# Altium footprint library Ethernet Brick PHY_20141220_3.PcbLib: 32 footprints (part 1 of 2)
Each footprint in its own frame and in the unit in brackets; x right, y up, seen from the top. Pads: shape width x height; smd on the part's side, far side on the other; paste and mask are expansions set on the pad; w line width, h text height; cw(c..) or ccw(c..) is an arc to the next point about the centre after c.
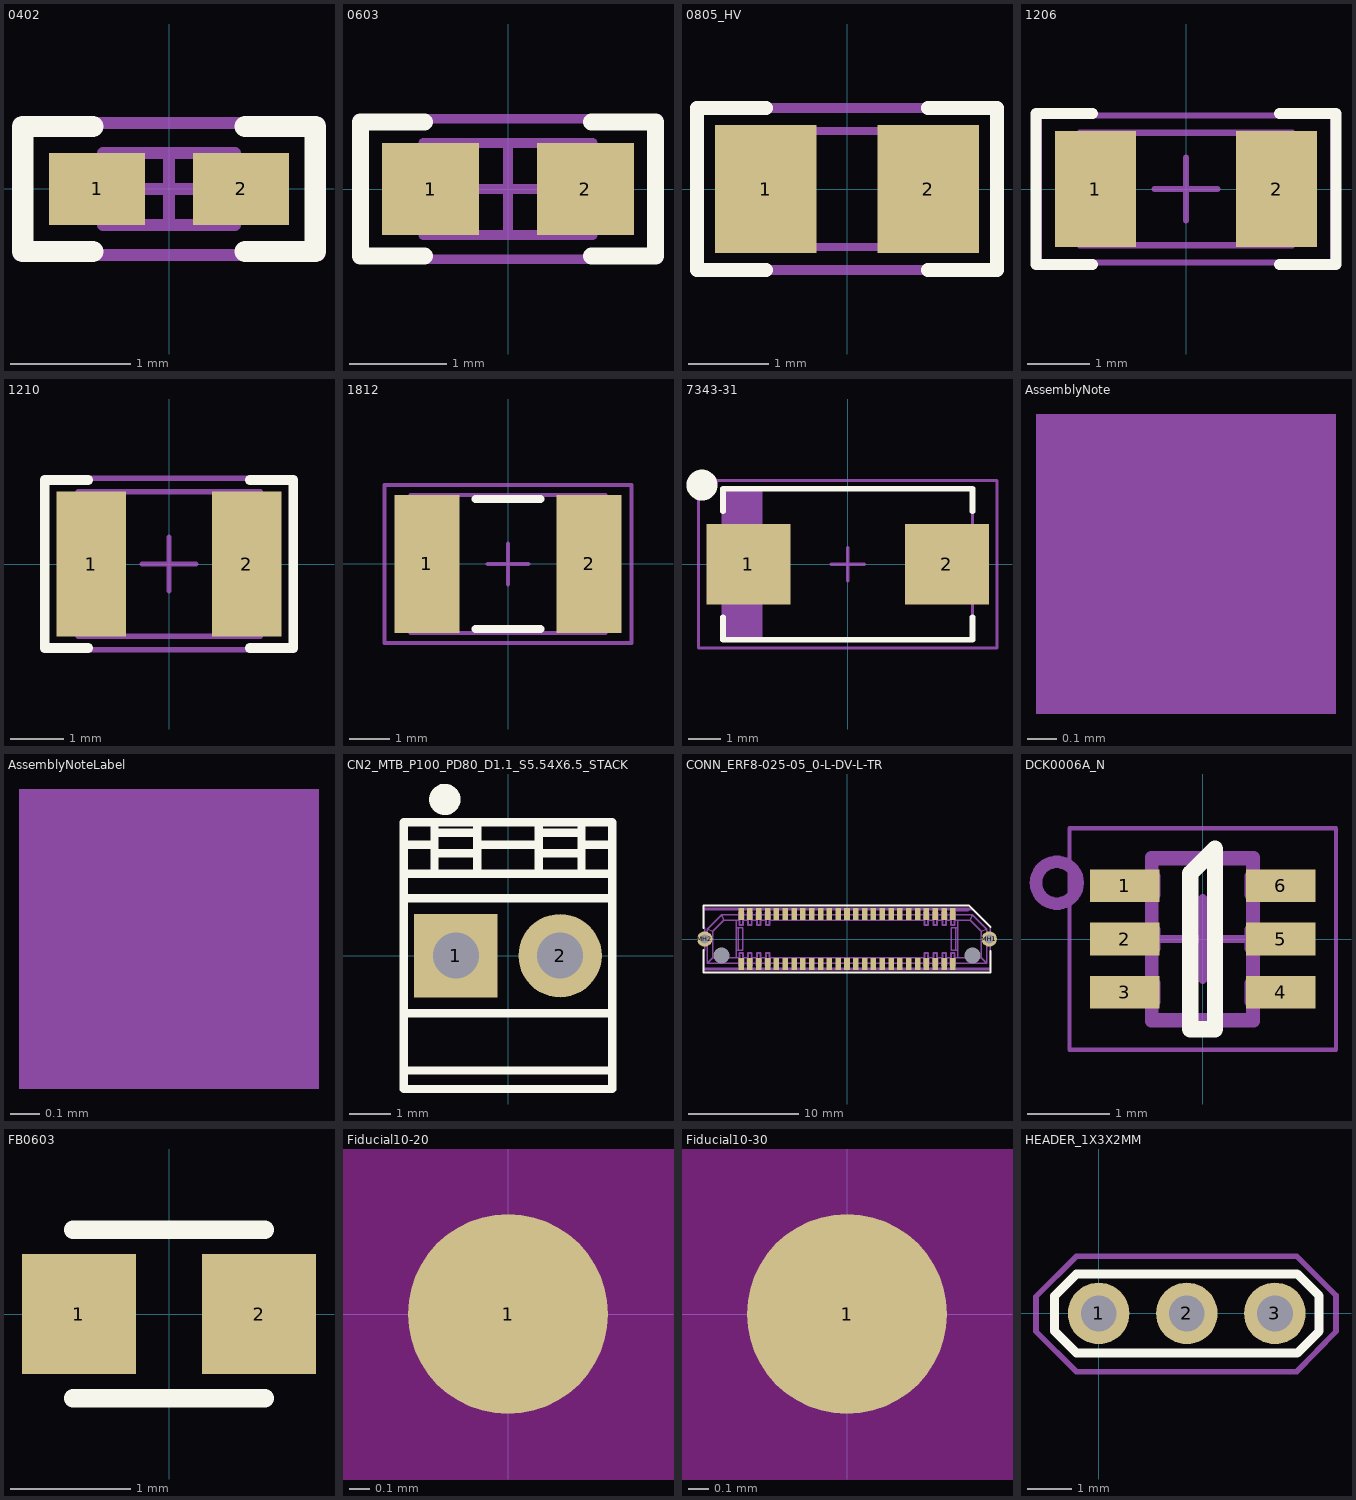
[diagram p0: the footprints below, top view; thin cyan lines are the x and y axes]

## 0402 [mm] "0402 from SM-752 data"
height 0.6
pads (2):
  rect 0.8x0.6 smd: 1(-0.6,0) 2(0.6,0)
Top Overlay:
  lines w0.178: -0.635,-0.521 -1.219,-0.521 -1.219,0.521 -0.635,0.521 ; 0.635,-0.521 1.219,-0.521 1.219,0.521 0.635,0.521
Mechanical 5:
  lines w0.1: -1.25,-0.55 1.25,-0.55 1.25,0.55 -1.25,0.55 -1.25,-0.55
  text ".Designator" at 2.502,-2.032 h0.91
Mechanical 13:
  lines w0.1: -0.35,-0.3 -0.35,0.3 ; 0.35,-0.3 0.35,0.3 ; -0.55,-0.3 -0.55,0.3 0.55,0.3 0.55,-0.3 -0.55,-0.3
Mechanical 15:
  lines w0.1: -0.3,0 0.3,0 ; 0,-0.3 0,0.3 ; -1.25,-0.55 -1.25,0.55 1.25,0.55 1.25,-0.55 -1.25,-0.55
3D body: height 0.6, standoff 0, extent -0.549,-0.299 -0.351,0.299
3D body: height 0.6, standoff 0, extent -0.349,-0.299 0.349,0.299
3D body: height 0.6, standoff 0, extent 0.351,-0.299 0.549,0.299

## 0603 [mm] "0603 from SM-752 data"
height 0.85
pads (2):
  rect 1x0.95 smd: 1(-0.8,0) 2(0.8,0)
Top Overlay:
  lines w0.178: -0.864,-0.691 -1.524,-0.691 -1.524,0.693 -0.864,0.693 ; 0.864,-0.691 1.524,-0.691 1.524,0.693 0.864,0.693
Mechanical 5:
  lines w0.1: -1.55,-0.725 -1.55,0.725 1.55,0.725 1.55,-0.725 -1.55,-0.725
  text ".Designator" at -0.813,-0.432 h0.91
Mechanical 13:
  lines w0.1: -0.55,-0.475 -0.55,0.475 ; 0.55,-0.475 0.55,0.475 ; -0.875,-0.475 0.875,-0.475 0.875,0.475 -0.875,0.475 -0.875,-0.475
Mechanical 15:
  lines w0.1: -0.475,0 0.475,0 ; 0,-0.475 0,0.475 ; -1.55,-0.725 1.55,-0.725 1.55,0.725 -1.55,0.725 -1.55,-0.725
3D body: height 0.85, standoff 0, extent -0.874,-0.474 -0.551,0.474
3D body: height 0.85, standoff 0, extent -0.549,-0.474 0.549,0.474
3D body: height 0.85, standoff 0, extent 0.551,-0.474 0.874,0.474

## 0805_HV [mil] "0805 with 30mil clearance between pads"
height 43.31
pads (2):
  rect 50x63 smd: 1(-40,0) 2(40,0)
Top Overlay:
  lines w7: -40,-40 -74,-40 -74,0 -74,40 -40,40 ; 40,-40 74,-40 74,0 74,40 40,40
Mechanical 5:
  lines w5: -74,-40 -74,40 74,40 74,-40 -74,-40
  text ".Designator" at 44,17.85 h36
Mechanical 13:
  lines w3.94: -25.59,-28.54 -25.59,28.54 ; 25.59,-28.54 25.59,28.54 ; -43.31,-28.54 43.31,-28.54 43.31,28.54 -43.31,28.54 -43.31,-28.54
3D body: height 43.31, standoff 0, extent -43.29,-28.52 -25.61,28.52
3D body: height 43.31, standoff 0, extent -25.57,-28.52 25.57,28.52
3D body: height 43.31, standoff 0, extent 25.61,-28.52 43.29,28.52

## 1206 [mm] "1206 from SM-752 data"
height 1.35
pads (2):
  rect 1.3x1.85 smd: 1(-1.45,0) 2(1.45,0)
Top Overlay:
  lines w0.178: -1.5,-1.21 -2.4,-1.21 -2.4,1.21 -1.5,1.21 ; 1.5,-1.21 2.4,-1.21 2.4,1.21 1.5,1.21
Mechanical 5:
  lines w0.1: -1.7,-0.9 1.7,-0.9 1.7,0.9 -1.7,0.9 -1.7,-0.9
  text ".Designator" at 0.711,0.457 h0.91
Mechanical 13:
  lines w0.1: -1.2,-0.9 -1.2,0.9 ; 1.2,-0.9 1.2,0.9 ; -1.7,-0.9 1.7,-0.9 1.7,0.9 -1.7,0.9 -1.7,-0.9
Mechanical 15:
  lines w0.1: -0.5,0 0.5,0 ; 0,-0.5 0,0.5 ; -2.35,-1.175 2.35,-1.175 2.35,1.175 -2.35,1.175 -2.35,-1.175
3D body: height 1.35, standoff 0, extent -1.699,-0.899 -1.201,0.899
3D body: height 1.35, standoff 0, extent -1.199,-0.899 1.199,0.899
3D body: height 1.35, standoff 0, extent 1.201,-0.899 1.699,0.899

## 1210 [mm] "1210 from SM-752 data"
height 1.35
pads (2):
  rect 1.3x2.7 smd: 1(-1.45,0) 2(1.45,0)
Top Overlay:
  lines w0.178: -1.511,-1.568 -2.316,-1.568 -2.316,1.568 -1.511,1.568 ; 1.511,-1.568 2.316,-1.568 2.316,1.568 1.511,1.568
Mechanical 5:
  lines w0.1: -1.7,-1.35 1.7,-1.35 1.7,1.35 -1.7,1.35 -1.7,-1.35
  text ".Designator" at 1.292,0.432 h0.91
Mechanical 13:
  lines w0.1: -1.2,-1.35 -1.2,1.35 ; 1.2,-1.35 1.2,1.35 ; -1.7,-1.35 -1.7,1.35 1.7,1.35 1.7,-1.35 -1.7,-1.35
Mechanical 15:
  lines w0.1: -0.5,0 0.5,0 ; 0,-0.5 0,0.5 ; -2.35,-1.6 -2.35,1.6 2.35,1.6 2.35,-1.6 -2.35,-1.6
3D body: height 1.35, standoff 0, extent -1.699,-1.349 -1.201,1.349
3D body: height 1.35, standoff 0, extent -1.199,-1.349 1.199,1.349
3D body: height 1.35, standoff 0, extent 1.201,-1.349 1.699,1.349

## 1812 [mm]
height 1.35
pads (2):
  rect 1.6x3.4 smd: 1(-2,0) 2(2,0)
Top Overlay:
  lines w0.2: -0.8,-1.6 0.8,-1.6 ; -0.8,1.6 0.8,1.6
Mechanical 5:
  lines w0.1: -2.4,-1.7 2.4,-1.7 2.4,1.7 -2.4,1.7 -2.4,-1.7
  text ".Designator" at -1.245,-0.406 h0.91
Mechanical 13:
  lines w0.1: -1.9,-1.7 -1.9,1.7 ; 1.9,-1.7 1.9,1.7 ; -2.4,-1.7 -2.4,1.7 2.4,1.7 2.4,-1.7 -2.4,-1.7
Mechanical 15:
  lines w0.1: -0.5,0 0.5,0 ; 0,-0.5 0,0.5 ; -3.05,-1.95 -3.05,1.95 3.05,1.95 3.05,-1.95 -3.05,-1.95
3D body: height 1.35, standoff 0, extent -2.399,-1.699 -1.901,1.699
3D body: height 1.35, standoff 0, extent -1.899,-1.699 1.899,1.699
3D body: height 1.35, standoff 0, extent 1.901,-1.699 2.399,1.699

## 7343-31 [mm] "Medium Density based on Kemet T495 dimensions"
height 3.1
pads (2):
  rect 2.55x2.45 smd: 1(-3.025,0) 2(3.025,0)
Top Overlay:
  circle w0.635: c-4.441,2.413 r0.152
  lines w0.178: -3.8,-1.614 -3.8,-2.3 3.8,-2.3 3.8,-1.614 ; -3.8,1.614 -3.8,2.3 3.8,2.3 3.8,1.614
Mechanical 5:
  rectangle: -3.8,-2.3 -2.65,2.3
  lines w0.1: -2.65,-2.3 -2.65,2.3 ; -3.8,-2.3 -3.8,2.3 3.8,2.3 3.8,-2.3 -3.8,-2.3
  text ".Designator" at -1.19,-0.457 h0.91
Mechanical 15:
  lines w0.1: -0.5,0 0.5,0 ; 0,-0.5 0,0.5 ; -4.55,-2.55 4.55,-2.55 4.55,2.55 -4.55,2.55 -4.55,-2.55
3D body: height 3.1, standoff 3.1, extent -3.799,-2.299 -2.651,2.299
3D body: height 3.1, standoff 0, extent -3.8,-2.3 3.8,2.3

## AssemblyNote [mm] "Assembly Note"
Mechanical 5:
  rectangle: -17.907,-39.319 -16.891,-38.303
  text ".Comment" at -16.256,-39.319 h0.91
  text ".Designator" at -21.59,-39.319 h0.91

## AssemblyNoteLabel [mm] "Assembly Note for PCB Labels"
Mechanical 5:
  rectangle: -17.907,-39.421 -16.891,-38.405
  text "Install label in silkscreened box after final wash.  Text shall be 8 pt font.  Text shall be per the Label Table in the PDF schematic." at -16.256,-39.421 h0.91
  text ".Designator" at -21.59,-39.421 h0.91

## CN2_MTB_P100_PD80_D1.1_S5.54X6.5_STACK [mil]
height 400
pads (2):
  rect 80x80 / inner round 80 / far side rect 80x80 hole 44: 1(-50,0)
  round 80 hole 44: 2(50,0)
Top Overlay:
  circle w10: c-60.63,149.95 r5
  circle w10: c-60.63,149.95 r10
  lines w8: -100,-110.24 100,-110.24 ; -100,-55.12 100,-55.12 ; -100,55.12 100,55.12 ; -100,78.74 100,78.74 ; -100,106.3 -70.87,106.3 ; -70.47,78.74 -70.47,127.95 ; -70.47,98.43 -31.5,98.43 ; -70.47,118.11 -31.5,118.11 ; -29.53,78.74 -29.53,127.95 ; -27.56,106.3 27.56,106.3 ; 29.53,78.74 29.53,127.95 ; 31.5,98.43 66.93,98.43 ; 31.5,118.11 66.93,118.11 ; 70.47,78.74 70.47,127.95 ; 70.87,106.3 100,106.3 ; -100,-127.95 -100,127.95 100,127.95 100,-127.95 -100,-127.95

## CONN_ERF8-025-05_0-L-DV-L-TR [mm] "Samtec 25X2 Header"
height 7.25
pads (54):
  rect 0.5x1.1 smd mask+0: 1(9.6,2.25) 2(9.6,-2.25) 3(8.8,2.25) 4(8.8,-2.25) 5(8,2.25) 6(8,-2.25) 7(7.2,2.25) 8(7.2,-2.25) 9(6.4,2.25) 10(6.4,-2.25) 11(5.6,2.25) 12(5.6,-2.25) 13(4.8,2.25) 14(4.8,-2.25) 15(4,2.25) 16(4,-2.25) 17(3.2,2.25) 18(3.2,-2.25) 19(2.4,2.25) 20(2.4,-2.25) 21(1.6,2.25) 22(1.6,-2.25) 23(0.8,2.25) 24(0.8,-2.25) 25(0,2.25) 26(0,-2.25) 27(-0.8,2.25) 28(-0.8,-2.25) 29(-1.6,2.25) 30(-1.6,-2.25) 31(-2.4,2.25) 32(-2.4,-2.25) 33(-3.2,2.25) 34(-3.2,-2.25) 35(-4,2.25) 36(-4,-2.25) 37(-4.8,2.25) 38(-4.8,-2.25) 39(-5.6,2.25) 40(-5.6,-2.25) 41(-6.4,2.25) 42(-6.4,-2.25) 43(-7.2,2.25) 44(-7.2,-2.25) 45(-8,2.25) 46(-8,-2.25) 47(-8.8,2.25) 48(-8.8,-2.25) 49(-9.6,2.25) 50(-9.6,-2.25)
  round 1.4 hole 0.838: MH1(12.9,0) MH2(-12.9,0)
  round 1 hole 1.45 unplated mask+0.508: MH3(11.4,-1.5) MH4(-11.4,-1.5)
Top Overlay:
  lines w0.178: -13,-1 -13,-2.65 -13,-3.05 13,-3.05 13,-2.65 13,-1.075 ; -13,1 -13,2.65 -13,3.05 11.05,3.05 11.45,2.65 13,1.1
Mechanical 5:
  drawing of 1952 lines, arcs and shapes, not listed
  text ".Designator" at -0.635,-0.299 h0.81
3D body: height 5.3, standoff -1.07, extent -13.027,-2.8 13.027,2.8

## DCK0006A_N [mm] "SOT23, 6-Leads, Body 2x1.3mm, Pitch 0.65mm, Lead Span 2.1mm, IPC Medium Density"
height 1.1
pads (6):
  rect 0.85x0.4 smd: 1(-0.95,0.65) 2(-0.95,0) 3(-0.95,-0.65) 4(0.95,-0.65) 5(0.95,0) 6(0.95,0.65)
Top Overlay:
  lines w0.2: -0.15,-1.1 0.15,-1.1 0.15,1.1 -0.15,0.8 -0.15,-1.1
Mechanical 5:
  lines w0.152: -0.613,-0.763 -0.613,-0.976 0.607,-0.976 0.607,-0.763 ; -0.613,-0.538 -0.613,-0.113 ; -0.613,0.112 -0.613,0.537 ; -0.613,0.762 -0.613,0.974 0.607,0.974 0.607,0.762 ; 0.607,-0.538 0.607,-0.113 ; 0.607,0.112 0.607,0.537 ; -0.628,-0.763 -0.591,-0.763 -0.591,-0.538 -0.628,-0.538 ; -0.628,-0.763 -0.853,-0.763 -0.865,-0.763 -0.959,-0.763 -1.143,-0.763 -1.143,-0.538 -0.959,-0.538 -0.865,-0.538 -0.853,-0.538 -0.628,-0.538 ; -0.628,-0.763 -0.628,-1.001 0.622,-1.001 0.622,-0.763 ; -0.628,-0.538 -0.628,-0.113 ; -0.628,-0.113 -0.591,-0.113 -0.591,0.112 -0.628,0.112 ; -0.628,-0.113 -0.853,-0.113 -0.865,-0.113 -0.959,-0.113 -1.143,-0.113 -1.143,0.112 -0.959,0.112 -0.865,0.112 -0.853,0.112 -0.628,0.112 ; -0.628,0.112 -0.628,0.537 ; -0.628,0.537 -0.591,0.537 -0.591,0.762 -0.628,0.762 ; -0.628,0.537 -0.853,0.537 -0.865,0.537 -0.959,0.537 -1.143,0.537 -1.143,0.762 -0.959,0.762 -0.865,0.762 -0.853,0.762 -0.628,0.762 ; -0.628,0.762 -0.628,0.999 0.622,0.999 0.622,0.762 ; 0.622,-0.763 0.585,-0.763 0.585,-0.538 0.622,-0.538 ; 0.622,-0.763 0.847,-0.763 0.859,-0.763 0.953,-0.763 1.137,-0.763 1.137,-0.538 0.953,-0.538 0.859,-0.538 0.847,-0.538 0.622,-0.538 ; 0.622,-0.538 0.622,-0.113 ; 0.622,-0.113 0.847,-0.113 0.859,-0.113 0.953,-0.113 1.137,-0.113 1.137,0.112 0.953,0.112 0.859,0.112 0.847,0.112 0.622,0.112 ; 0.622,-0.113 0.585,-0.113 0.585,0.112 0.622,0.112 ; 0.622,0.112 0.622,0.537 ; 0.622,0.537 0.585,0.537 0.585,0.762 0.622,0.762 ; 0.622,0.537 0.847,0.537 0.859,0.537 0.953,0.537 1.137,0.537 1.137,0.762 0.953,0.762 0.859,0.762 0.847,0.762 0.622,0.762 ; -2.032,0.686 ccw(c-1.778,0.686) -1.524,0.686 ccw(c-1.778,0.686) -2.032,0.686
  text ".Designator" at 0.432,1.524 h0.91
Mechanical 15:
  lines w0.05: -1.625,-1.35 1.625,-1.35 1.625,1.35 -1.625,1.35 -1.625,-1.35
  lines w0.1: -0.5,0 0.5,0 ; 0,-0.5 0,0.5
3D body: height 0.94, standoff -0.01, extent -1.14,-1 1.14,1

## FB0603 [mm]
height 0.95
pads (2):
  rect 0.95x1 smd: 1(-0.75,0) 2(0.75,0)
Top Overlay:
  lines w0.152: -0.8,-0.703 0.8,-0.703 ; -0.8,0.703 0.8,0.703
Mechanical 15:
  lines w0.025: -0.8,-0.4 -0.8,0.4 ; 0.8,-0.4 0.8,0.4
  lines w0.1: -0.8,-0.4 -0.8,0.4

## Fiducial10-20 [mm]
pads (1):
  round 1 smd mask+0.5: 1(0,0)
Top Layer keep-out:
  circle w1.678: c0,0 r0.75

## Fiducial10-30 [mm]
pads (1):
  round 1 smd mask+0.508: 1(0,0)
Top Layer keep-out:
  circle w1.678: c0,0 r0.75

## HEADER_1X3X2MM [mil]
pads (3):
  round 55 hole 32: 1(0,0) 2(78.7,0) 3(157.44,0)
Top Overlay:
  lines w8: -39.37,-15.75 -39.37,15.75 -19.69,35.43 177.17,35.43 196.85,15.75 196.85,-15.75 177.17,-35.43 -19.69,-35.43 -39.37,-15.75
Mechanical 5:
  lines w5: -56,-16 -56,15 -20,51 177,51 212,16 212,-16 177,-52 -20,-52 -56,-16
  text "*" at -44,-15 h36
  text ".Designator" at 110,23.5 h36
